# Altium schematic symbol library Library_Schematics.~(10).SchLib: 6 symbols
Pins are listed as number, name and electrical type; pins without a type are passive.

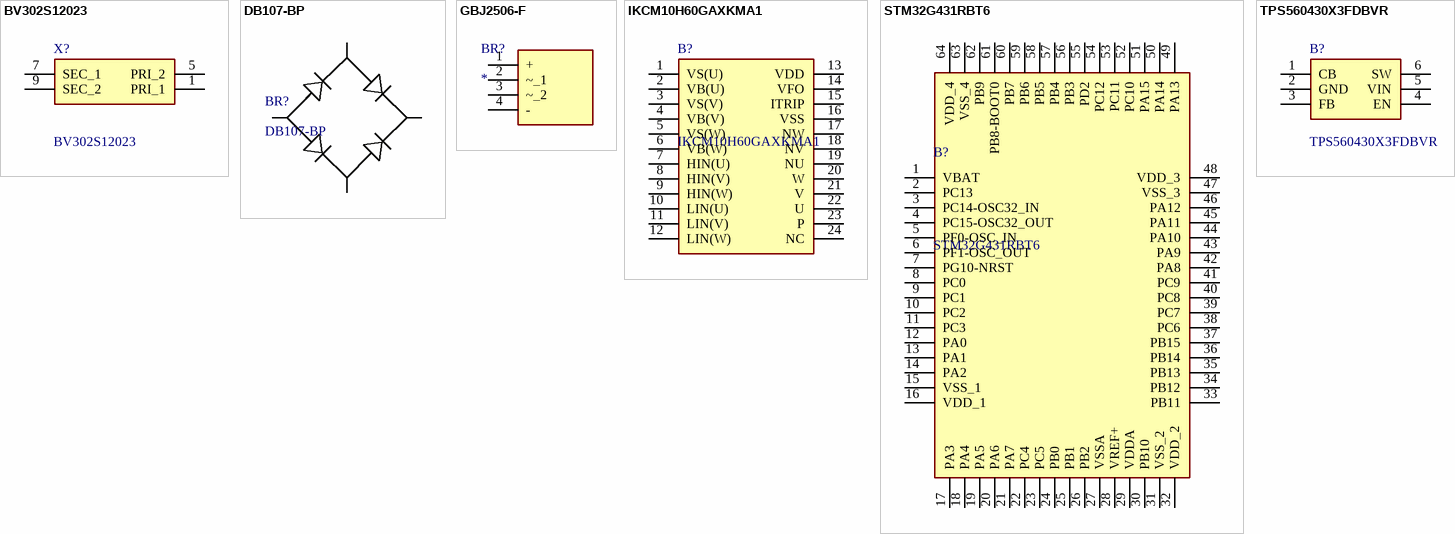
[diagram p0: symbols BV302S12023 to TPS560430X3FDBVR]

## BV302S12023
designator X?
2.3VA Encapsulated Transformer 50/60Hz; Manufacturer_Name: Zettler Group; Geometry.Height: 29.8mm
footprint 899_BV302S12023
pins: 1 PRI_1, 5 PRI_2, 7 SEC_1, 9 SEC_2

## DB107-BP
designator BR?
Description; Manufacturer_Name: MCC
footprint 898_DB-1_MCC
pins: 1, 2, 3, 4

## GBJ2506-F
designator BR?
Bridge Rectifier; Manufacturer_Name: Diodes Incorporated; Manufacturer_Part_Number: GBJ2506-F
footprint 996_GBJ_1
pins: 1 +, 2 ~_1, 3 ~_2, 4 -

## IKCM10H60GAXKMA1
designator B?
Intelligent Power Module 3-Ph 600V 10A; Manufacturer_Name: Infineon; Geometry.Height: 5.6mm
footprint 997_IKCM10H60GAXKMA1
pins: 1 VS(U), 2 VB(U), 3 VS(V), 4 VB(V), 5 VS(W), 6 VB(W), 7 HIN(U), 8 HIN(V), 9 HIN(W), 10 LIN(U), 11 LIN(V), 12 LIN(W), 13 VDD, 14 VFO, 15 ITRIP, 16 VSS, 17 NW, 18 NV, 19 NU, 20 W, 21 V, 22 U, 23 P, 24 NC

## STM32G431RBT6
designator B?
ARM Microcontrollers - MCU Mainstream Arm Cortex-M4+ MCU 170MHz with 128Kbytes of Flash memory, Math Accelerator, Medium Analog level integration; Manufacturer_Name: STMicroelectronics; Geometry.Height: 1.6mm
footprint 999_QFP50P1200X1200X160-64N
pins: 1 VBAT, 2 PC13, 3 PC14-OSC32_IN, 4 PC15-OSC32_OUT, 5 PF0-OSC_IN, 6 PF1-OSC_OUT, 7 PG10-NRST, 8 PC0, 9 PC1, 10 PC2, 11 PC3, 12 PA0, 13 PA1, 14 PA2, 15 VSS_1, 16 VDD_1, 17 PA3, 18 PA4, 19 PA5, 20 PA6, 21 PA7, 22 PC4, 23 PC5, 24 PB0, 25 PB1, 26 PB2, 27 VSSA, 28 VREF+, 29 VDDA, 30 PB10, 31 VSS_2, 32 VDD_2, 33 PB11, 34 PB12, 35 PB13, 36 PB14, 37 PB15, 38 PC6, 39 PC7, 40 PC8, 41 PC9, 42 PA8, 43 PA9, 44 PA10, 45 PA11, 46 PA12, 47 VSS_3, 48 VDD_3, 49 PA13, 50 PA14, 51 PA15, 52 PC10, 53 PC11, 54 PC12, 55 PD2, 56 PB3, 57 PB4, 58 PB5, 59 PB6, 60 PB7, 61 PB8-BOOT0, 62 PB9, 63 VSS_4, 64 VDD_4

## TPS560430X3FDBVR
designator B?
SIMPLE SWITCHER 36-V, 600-mA Buck Regulator With High-Efficiency Sleep Mode; Manufacturer_Name: Texas Instruments; Geometry.Height: 1.45mm
footprint 998_SOT95P280X145-6N
pins: 1 CB, 2 GND, 3 FB, 4 EN, 5 VIN, 6 SW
